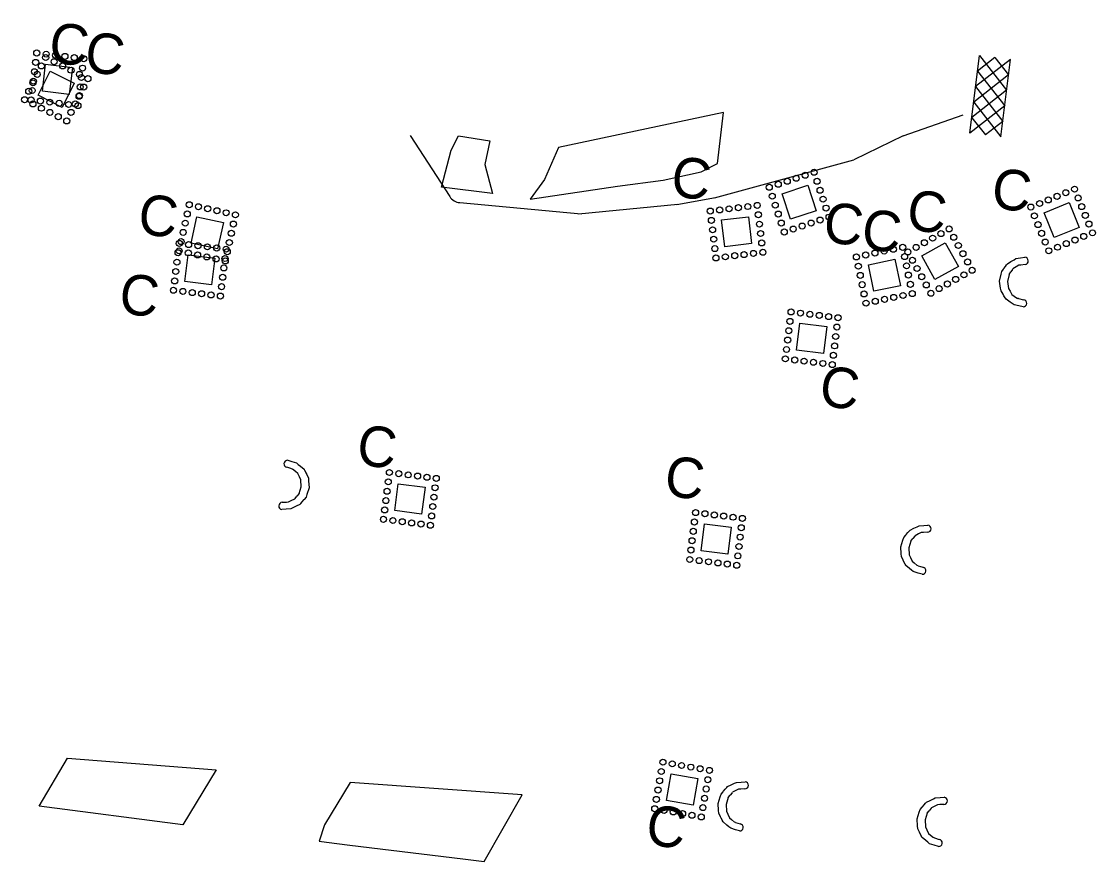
# Model space of a CAD drawing. Extents: x 2470000 to 2520000, y 340000 to 380000.
# Drawn here: x 2482594.7 to 2482992.6, y 365832.6 to 366143.9 of the extents above; entities that cross this region are included whole.
import ezdxf

# ---------------------------------------------------------------- set-up
doc = ezdxf.new("R2010")
doc.units = 0
for name, color, linetype in [('ESA Hatching CG', 7, 'Continuous'), ('Label C CG CELL', 7, 'Continuous'), ('Prop Guardrail', 7, 'Continuous'), ('Prop Guardrail Anchor Unit CELL', 7, 'Continuous'), ('Prop Structure Anchor Unit CELL', 7, 'Continuous'), ('Rock Inlet Sediment Trap Type C CG CELL', 7, 'Continuous'), ('Rock Silt Check Type A Final CELL', 7, 'Continuous'), ('Scratch_Level_5', 7, 'Continuous'), ('Sheet Data Field CELL', 7, 'Continuous'), ('Wattle Both CELL', 7, 'Continuous'), ('Wattle CG CELL', 7, 'Continuous')]:
    doc.layers.add(name, color=color, linetype=linetype)

# ---------------------------------------------------------------- blocks, each defined once
blk = doc.blocks.new('C2')
at = {"layer": 'Prop Guardrail Anchor Unit CELL'}
blk.add_text('C', height=0.3, dxfattribs=at).set_placement((-0.161, -0.136))
blk = doc.blocks.new('C3')
at = {"layer": 'Prop Guardrail'}
blk.add_text('C', height=0.3, dxfattribs=at).set_placement((-0.161, -0.136))
blk = doc.blocks.new('C1')
at = {"layer": 'Label C CG CELL'}
blk.add_text('C', height=0.3, dxfattribs=at).set_placement((-0.161, -0.136))

msp = doc.modelspace()

# ---------------------------------------------------------------- linework, layer by layer
at = {"layer": 'ESA Hatching CG'}
for points in [[(2482783.17, 366078.02), (2482815.48, 366082.81), (2482832.39, 366085.11), (2482846.44, 366088.2), (2482852.5, 366091.17), (2482854.82, 366110.14), (2482793.62, 366097.16), (2482788.43, 366085.25)], [(2482768.25, 366099.58), (2482766.41, 366090.91), (2482769.18, 366080.17), (2482750.25, 366082.49), (2482753.9, 366096.19), (2482756.63, 366101.54)], [(2482666.88, 365866.58), (2482654.45, 365846.17), (2482601.26, 365853.13), (2482611.74, 365870.81)], [(2482716.53, 365861.91), (2482706.94, 365846.13), (2482704.95, 365840.13), (2482707.69, 365839.74), (2482716.32, 365838.68), (2482758.24, 365833.54), (2482766.16, 365832.57), (2482780.17, 365857.27)]]:
    msp.add_lwpolyline(points, close=True, dxfattribs=at)
at = {"layer": 'Prop Structure Anchor Unit CELL'}
for points in [[(2482847.68, 365957.67), (2482857.61, 365956.45), (2482856.39, 365946.52), (2482846.46, 365947.75)], [(2482835.37, 365865.01), (2482845.22, 365863.28), (2482843.48, 365853.43), (2482833.63, 365855.18)]]:
    msp.add_lwpolyline(points, close=True, dxfattribs=at)
for centre in [(2482844.41, 365961.86), (2482847.88, 365961.44), (2482851.36, 365961.01), (2482854.83, 365960.58), (2482858.31, 365960.16), (2482861.78, 365959.73), (2482843.98, 365958.39), (2482861.35, 365956.26), (2482843.13, 365951.44), (2482843.56, 365954.92), (2482860.93, 365952.78), (2482842.7, 365947.97), (2482860.5, 365949.31), (2482842.28, 365944.49), (2482845.75, 365944.07), (2482849.22, 365943.64), (2482852.7, 365943.21), (2482860.07, 365945.83), (2482856.17, 365942.79), (2482859.65, 365942.36), (2482832.32, 365869.38), (2482835.77, 365868.77), (2482839.21, 365868.16), (2482842.66, 365867.55), (2482831.71, 365865.93), (2482846.11, 365866.95), (2482849.56, 365866.34), (2482831.1, 365862.48), (2482848.95, 365862.89), (2482829.89, 365855.59), (2482830.5, 365859.04), (2482847.73, 365856), (2482848.34, 365859.44), (2482829.28, 365852.14), (2482832.73, 365851.54), (2482847.12, 365852.55), (2482836.17, 365850.93), (2482839.62, 365850.32), (2482843.07, 365849.71), (2482846.52, 365849.1)]:
    msp.add_circle(centre, 1.12, dxfattribs=at)
at = {"layer": 'Rock Inlet Sediment Trap Type C CG CELL'}
for points in [[(2482603.65, 366127.98), (2482613.58, 366126.76), (2482612.36, 366116.83), (2482602.44, 366118.06)], [(2482876.49, 366080.05), (2482885.98, 366083.21), (2482889.14, 366073.72), (2482879.64, 366070.58)], [(2482928.18, 366056.98), (2482936.92, 366061.85), (2482941.78, 366053.12), (2482933.04, 366048.26)], [(2482883.08, 366032.01), (2482893, 366030.79), (2482891.78, 366020.87), (2482881.86, 366022.1)]]:
    msp.add_lwpolyline(points, close=True, dxfattribs=at)
for centre in [(2482600.38, 366132.18), (2482603.86, 366131.75), (2482607.33, 366131.32), (2482610.8, 366130.9), (2482614.28, 366130.47), (2482617.75, 366130.04), (2482599.96, 366128.7), (2482617.33, 366126.57), (2482599.53, 366125.23), (2482616.9, 366123.1), (2482598.68, 366118.28), (2482599.1, 366121.75), (2482616.47, 366119.62), (2482598.25, 366114.81), (2482601.72, 366114.38), (2482616.05, 366116.15), (2482605.2, 366113.95), (2482608.67, 366113.53), (2482612.14, 366113.1), (2482615.62, 366112.67), (2482885.02, 366086.86), (2482888.34, 366087.97), (2482871.73, 366082.44), (2482875.05, 366083.55), (2482878.37, 366084.65), (2482881.69, 366085.76), (2482889.44, 366084.65), (2482872.84, 366079.12), (2482890.55, 366081.33), (2482873.94, 366075.8), (2482891.65, 366078.01), (2482892.76, 366074.69), (2482875.05, 366072.48), (2482893.87, 366071.36), (2482876.16, 366069.16), (2482880.58, 366066.94), (2482883.9, 366068.05), (2482887.22, 366069.15), (2482890.54, 366070.26), (2482938.35, 366066.97), (2482877.26, 366065.84), (2482932.24, 366063.56), (2482935.29, 366065.26), (2482940.05, 366063.91), (2482923.06, 366058.45), (2482926.12, 366060.15), (2482929.18, 366061.85), (2482941.76, 366060.85), (2482924.77, 366055.39), (2482943.46, 366057.79), (2482945.17, 366054.74), (2482926.47, 366052.33), (2482946.87, 366051.68), (2482928.18, 366049.27), (2482937.7, 366046.57), (2482940.76, 366048.27), (2482943.81, 366049.97), (2482929.88, 366046.22), (2482931.58, 366043.16), (2482934.64, 366044.86), (2482879.81, 366036.21), (2482883.28, 366035.78), (2482886.75, 366035.36), (2482890.23, 366034.93), (2482879.38, 366032.73), (2482893.7, 366034.5), (2482896.75, 366030.6), (2482897.18, 366034.08), (2482878.95, 366029.26), (2482896.32, 366027.13), (2482878.53, 366025.79), (2482895.9, 366023.65), (2482877.67, 366018.84), (2482878.1, 366022.31), (2482895.47, 366020.18), (2482881.15, 366018.41), (2482884.62, 366017.99), (2482888.09, 366017.56), (2482891.57, 366017.13), (2482895.04, 366016.71)]:
    msp.add_circle(centre, 1.12, dxfattribs=at)
at = {"layer": 'Rock Silt Check Type A Final CELL'}
for p, q in [((2482946.05, 366102.53), (2482949.57, 366131.22)), ((2482949.57, 366131.22), (2482959.63, 366118.35)), ((2482961.04, 366129.81), (2482948.17, 366119.75)), ((2482955.28, 366130.53), (2482948.86, 366125.46)), ((2482955.28, 366130.53), (2482960.33, 366124.05)), ((2482957.52, 366101.13), (2482961.04, 366129.81)), ((2482960.33, 366124.05), (2482947.46, 366114)), ((2482948.86, 366125.46), (2482958.92, 366112.59)), ((2482948.17, 366119.75), (2482958.22, 366106.83)), ((2482959.63, 366118.35), (2482946.75, 366108.24)), ((2482958.92, 366112.59), (2482946.05, 366102.53)), ((2482947.46, 366114), (2482957.52, 366101.13)), ((2482946.8, 366108.18), (2482951.76, 366101.82)), ((2482958.22, 366106.83), (2482951.76, 366101.82))]:
    msp.add_line(p, q, dxfattribs=at)
at = {"layer": 'Scratch_Level_5'}
for points in [[(2482605.35, 366125.45), (2482614.29, 366120.97), (2482609.81, 366112.03), (2482600.87, 366116.52)], [(2482973.52, 366073.01), (2482982.77, 366076.81), (2482986.57, 366067.56), (2482977.31, 366063.77)], [(2482854.05, 366070.31), (2482863.98, 366071.51), (2482865.18, 366061.59), (2482855.25, 366060.4)], [(2482659.72, 366071.47), (2482669.49, 366069.33), (2482667.34, 366059.56), (2482657.58, 366061.71)], [(2482656.42, 366057.42), (2482666.35, 366056.2), (2482665.13, 366046.28), (2482655.21, 366047.51)], [(2482908.45, 366053.68), (2482918.24, 366055.72), (2482920.27, 366045.92), (2482910.47, 366043.9)], [(2482734.27, 365972.52), (2482744.19, 365971.27), (2482742.93, 365961.34), (2482733.01, 365962.61)]]:
    msp.add_lwpolyline(points, close=True, dxfattribs=at)
for centre in [(2482603.68, 366130.51), (2482602.11, 366127.38), (2482606.81, 366128.94), (2482609.94, 366127.37), (2482600.54, 366124.25), (2482613.06, 366125.8), (2482616.19, 366124.23), (2482619.32, 366122.66), (2482598.97, 366121.12), (2482617.75, 366119.54), (2482595.84, 366114.86), (2482597.4, 366117.99), (2482616.19, 366116.41), (2482598.97, 366113.29), (2482602.09, 366111.72), (2482605.22, 366110.16), (2482613.05, 366110.15), (2482614.62, 366113.28), (2482608.35, 366108.59), (2482611.48, 366107.02), (2482978.32, 366079.06), (2482981.56, 366080.39), (2482984.8, 366081.72), (2482986.13, 366078.48), (2482656.86, 366075.96), (2482660.27, 366075.21), (2482663.69, 366074.46), (2482856.82, 366074.44), (2482860.3, 366074.86), (2482863.77, 366075.28), (2482867.25, 366075.7), (2482968.61, 366075.07), (2482971.85, 366076.4), (2482975.08, 366077.73), (2482987.46, 366075.25), (2482656.11, 366072.54), (2482667.11, 366073.71), (2482670.53, 366072.96), (2482673.95, 366072.21), (2482849.87, 366073.6), (2482853.35, 366074.02), (2482867.67, 366072.23), (2482969.94, 366071.83), (2482988.79, 366072.01), (2482655.36, 366069.12), (2482673.2, 366068.79), (2482850.29, 366070.13), (2482850.71, 366066.66), (2482868.09, 366068.76), (2482971.27, 366068.59), (2482990.12, 366068.77), (2482654.61, 366065.7), (2482672.45, 366065.37), (2482851.13, 366063.18), (2482868.51, 366065.28), (2482972.6, 366065.36), (2482984.97, 366062.87), (2482988.21, 366064.2), (2482991.45, 366065.53), (2482653.11, 366058.86), (2482653.15, 366061.62), (2482653.86, 366062.28), (2482656.63, 366061.19), (2482660.1, 366060.77), (2482663.58, 366060.34), (2482667.05, 366059.91), (2482670.52, 366059.49), (2482670.95, 366058.53), (2482671.7, 366061.95), (2482851.55, 366059.71), (2482868.93, 366061.81), (2482914.28, 366058.74), (2482917.71, 366059.45), (2482921.14, 366060.17), (2482973.93, 366062.12), (2482975.26, 366058.88), (2482978.5, 366060.21), (2482981.73, 366061.54), (2482652.3, 366054.67), (2482652.73, 366058.15), (2482656.52, 366058.11), (2482659.94, 366057.36), (2482663.36, 366056.61), (2482666.78, 366055.86), (2482670.1, 366056.01), (2482670.2, 366055.11), (2482851.97, 366056.23), (2482855.45, 366056.65), (2482858.92, 366057.07), (2482862.4, 366057.49), (2482865.87, 366057.91), (2482869.35, 366058.33), (2482904, 366056.61), (2482907.43, 366057.32), (2482910.85, 366058.03), (2482921.85, 366056.74), (2482651.87, 366051.2), (2482669.67, 366052.54), (2482904.71, 366053.18), (2482922.56, 366053.31), (2482651.45, 366047.72), (2482669.24, 366049.06), (2482905.42, 366049.76), (2482923.27, 366049.88), (2482651.02, 366044.25), (2482654.49, 366043.82), (2482657.97, 366043.4), (2482661.44, 366042.97), (2482664.92, 366042.54), (2482668.82, 366045.59), (2482906.13, 366046.33), (2482906.84, 366042.9), (2482923.98, 366046.46), (2482924.69, 366043.03), (2482668.39, 366042.12), (2482907.55, 366039.48), (2482910.98, 366040.19), (2482914.41, 366040.9), (2482917.84, 366041.61), (2482921.26, 366042.32), (2482731.01, 365976.73), (2482734.48, 365976.29), (2482737.96, 365975.85), (2482741.43, 365975.41), (2482744.9, 365974.97), (2482730.57, 365973.26), (2482747.93, 365971.06), (2482748.37, 365974.53), (2482730.13, 365969.78), (2482747.49, 365967.59), (2482729.69, 365966.31), (2482747.05, 365964.12), (2482728.81, 365959.37), (2482729.25, 365962.84), (2482746.62, 365960.64), (2482732.29, 365958.93), (2482735.76, 365958.49), (2482739.23, 365958.05), (2482742.7, 365957.61), (2482746.18, 365957.17)]:
    msp.add_circle(centre, 1.12, dxfattribs=at)
at = {"layer": 'Sheet Data Field CELL'}
for p, q in [((2482921.28, 366101.43), (2482943.54, 366109.3)), ((2482738.64, 366101.6), (2482753.33, 366078.99)), ((2482921.28, 366101.43), (2482903.07, 366092.59)), ((2482851.41, 366078.54), (2482903.07, 366092.59)), ((2482757.06, 366076.74), (2482802.05, 366072.55)), ((2482801.1, 366072.54), (2482837.85, 366076.12)), ((2482837.45, 366076.07), (2482851.84, 366078.64))]:
    msp.add_line(p, q, dxfattribs=at)
msp.add_arc((2482757.52, 366081.71), 5, 213.0274, 264.68, dxfattribs=at)
at = {"layer": 'Wattle Both CELL'}
for p, q in [((2482694.82, 365978.1), (2482693.05, 365978.67)), ((2482694.82, 365978.1), (2482695.14, 365978)), ((2482696.27, 365977.05), (2482695.14, 365978)), ((2482697.06, 365976.39), (2482696.27, 365977.05)), ((2482697.67, 365975.08), (2482697.06, 365976.39)), ((2482698.18, 365973.99), (2482697.67, 365975.08)), ((2482698.29, 365971.45), (2482698.18, 365973.99)), ((2482697.52, 365968.92), (2482696.77, 365968)), ((2482697.52, 365968.92), (2482698.29, 365971.44)), ((2482698.29, 365971.45), (2482698.29, 365971.44)), ((2482691.3, 365965.68), (2482692.85, 365965.76)), ((2482692.85, 365965.76), (2482693.64, 365965.81)), ((2482693.64, 365965.81), (2482694.63, 365966.3)), ((2482694.63, 365966.3), (2482695.93, 365966.95)), ((2482696.08, 365967.13), (2482695.93, 365966.95)), ((2482696.08, 365967.13), (2482696.77, 365968)), ((2482924.15, 365951.33), (2482924.9, 365952.26)), ((2482925.6, 365953.12), (2482924.9, 365952.26)), ((2482925.6, 365953.12), (2482925.75, 365953.3)), ((2482927.05, 365953.95), (2482925.75, 365953.3)), ((2482928.03, 365954.44), (2482927.05, 365953.95)), ((2482928.82, 365954.49), (2482928.03, 365954.44)), ((2482930.37, 365954.57), (2482928.82, 365954.49)), ((2482924.15, 365951.33), (2482923.38, 365948.82)), ((2482923.38, 365948.8), (2482923.38, 365948.82)), ((2482923.38, 365948.8), (2482923.5, 365946.27)), ((2482923.5, 365946.27), (2482924, 365945.17)), ((2482924, 365945.17), (2482924.61, 365943.86)), ((2482924.61, 365943.86), (2482925.4, 365943.2)), ((2482925.4, 365943.2), (2482926.54, 365942.26)), ((2482926.85, 365942.16), (2482926.54, 365942.26)), ((2482926.85, 365942.16), (2482928.63, 365941.59)), ((2482856.5, 365856.24), (2482857.24, 365857.17)), ((2482857.94, 365858.03), (2482857.24, 365857.17)), ((2482857.94, 365858.03), (2482858.09, 365858.21)), ((2482859.39, 365858.86), (2482858.09, 365858.21)), ((2482860.38, 365859.35), (2482859.39, 365858.86)), ((2482861.17, 365859.4), (2482860.38, 365859.35)), ((2482862.72, 365859.48), (2482861.17, 365859.4)), ((2482856.5, 365856.24), (2482855.72, 365853.72)), ((2482855.72, 365853.71), (2482855.72, 365853.72)), ((2482855.72, 365853.71), (2482855.84, 365851.17)), ((2482933.08, 365853.11), (2482931.78, 365852.46)), ((2482934.07, 365853.6), (2482933.08, 365853.11)), ((2482934.86, 365853.64), (2482934.07, 365853.6)), ((2482936.41, 365853.73), (2482934.86, 365853.64)), ((2482855.84, 365851.17), (2482856.34, 365850.08)), ((2482856.34, 365850.08), (2482856.95, 365848.77)), ((2482856.95, 365848.77), (2482857.74, 365848.11)), ((2482930.19, 365850.48), (2482929.42, 365847.97)), ((2482930.19, 365850.48), (2482930.94, 365851.41)), ((2482931.63, 365852.28), (2482930.94, 365851.41)), ((2482931.63, 365852.28), (2482931.78, 365852.46)), ((2482857.74, 365848.11), (2482858.88, 365847.17)), ((2482859.2, 365847.06), (2482858.88, 365847.17)), ((2482859.2, 365847.06), (2482860.97, 365846.5)), ((2482929.42, 365847.96), (2482929.42, 365847.97)), ((2482929.42, 365847.96), (2482929.53, 365845.42)), ((2482929.53, 365845.42), (2482930.04, 365844.33)), ((2482930.04, 365844.33), (2482930.65, 365843.01)), ((2482930.65, 365843.01), (2482931.44, 365842.36)), ((2482931.44, 365842.36), (2482932.57, 365841.41)), ((2482932.89, 365841.31), (2482932.57, 365841.41)), ((2482932.89, 365841.31), (2482934.66, 365840.74))]:
    msp.add_line(p, q, dxfattribs=at)
for points in [[(2482693.36, 365981.24), (2482694.86, 365980.79), (2482696.59, 365980.26), (2482697.24, 365979.73), (2482698.02, 365979.09), (2482699.4, 365977.94), (2482699.42, 365977.91), (2482699.61, 365977.51), (2482699.65, 365977.44), (2482700.07, 365976.59), (2482700.36, 365975.99), (2482701.01, 365974.67), (2482701.08, 365973.63), (2482701.24, 365971.09), (2482701.24, 365971.08), (2482700.44, 365968.57), (2482700.12, 365967.59), (2482699.39, 365966.73), (2482699.23, 365966.54), (2482698.61, 365965.81), (2482698.13, 365965.26), (2482698.02, 365965.13), (2482697.78, 365964.85), (2482697.78, 365964.85), (2482696.41, 365964.19), (2482695.21, 365963.6), (2482694.48, 365963.25), (2482692.72, 365963.13), (2482691.18, 365963.02)], [(2482928.31, 365939.01), (2482926.82, 365939.46), (2482925.08, 365939.99), (2482924.44, 365940.52), (2482923.66, 365941.17), (2482922.27, 365942.31), (2482922.26, 365942.35), (2482922.06, 365942.74), (2482922.03, 365942.81), (2482921.6, 365943.67), (2482921.31, 365944.27), (2482920.67, 365945.58), (2482920.6, 365946.62), (2482920.43, 365949.17), (2482920.43, 365949.18), (2482921.24, 365951.69), (2482921.55, 365952.67), (2482922.29, 365953.53), (2482922.44, 365953.71), (2482923.07, 365954.44), (2482923.54, 365955), (2482923.65, 365955.12), (2482923.89, 365955.4), (2482923.9, 365955.41), (2482925.26, 365956.07), (2482926.47, 365956.65), (2482927.2, 365957), (2482928.95, 365957.12), (2482930.49, 365957.23)], [(2482860.65, 365843.92), (2482859.16, 365844.37), (2482857.42, 365844.9), (2482856.78, 365845.43), (2482856, 365846.08), (2482854.62, 365847.22), (2482854.6, 365847.26), (2482854.4, 365847.65), (2482854.37, 365847.72), (2482853.95, 365848.58), (2482853.65, 365849.18), (2482853.01, 365850.49), (2482852.94, 365851.53), (2482852.77, 365854.07), (2482852.77, 365854.09), (2482853.58, 365856.6), (2482853.9, 365857.58), (2482854.63, 365858.44), (2482854.79, 365858.62), (2482855.41, 365859.35), (2482855.88, 365859.9), (2482856, 365860.03), (2482856.24, 365860.31), (2482856.24, 365860.32), (2482857.6, 365860.98), (2482858.81, 365861.56), (2482859.54, 365861.91), (2482861.29, 365862.03), (2482862.84, 365862.14)], [(2482934.35, 365838.16), (2482932.85, 365838.62), (2482931.12, 365839.14), (2482930.47, 365839.68), (2482929.69, 365840.32), (2482928.31, 365841.46), (2482928.29, 365841.5), (2482928.1, 365841.9), (2482928.06, 365841.96), (2482927.64, 365842.82), (2482927.35, 365843.42), (2482926.7, 365844.73), (2482926.63, 365845.77), (2482926.47, 365848.32), (2482926.47, 365848.33), (2482927.27, 365850.84), (2482927.59, 365851.82), (2482928.32, 365852.68), (2482928.48, 365852.86), (2482929.1, 365853.59), (2482929.58, 365854.15), (2482929.69, 365854.28), (2482929.93, 365854.56), (2482929.93, 365854.56), (2482931.29, 365855.22), (2482932.5, 365855.8), (2482933.23, 365856.15), (2482934.98, 365856.28), (2482936.53, 365856.39)]]:
    msp.add_lwpolyline(points, dxfattribs=at)
for centre, radius, start, end in [((2482693.21, 365979.96), 1.3, 83.0023, 263.0023), ((2482691.34, 365964.35), 1.33, 91.8897, 263.0023), ((2482930.33, 365955.91), 1.33, 271.8897, 83.0023), ((2482928.47, 365940.3), 1.3, 263.0023, 83.0023), ((2482862.67, 365860.82), 1.33, 271.8897, 83.0023), ((2482936.37, 365855.06), 1.33, 271.8897, 83.0023), ((2482860.81, 365845.21), 1.3, 263.0023, 83.0023), ((2482934.5, 365839.45), 1.3, 263.0023, 83.0023)]:
    msp.add_arc(centre, radius, start, end, dxfattribs=at)
at = {"layer": 'Wattle CG CELL'}
for p, q in [((2482961.83, 366051.97), (2482961.21, 366051.05)), ((2482961.83, 366051.97), (2482961.96, 366052.17)), ((2482963.2, 366052.92), (2482961.96, 366052.17)), ((2482964.15, 366053.5), (2482963.2, 366052.92)), ((2482964.93, 366053.61), (2482964.15, 366053.5)), ((2482966.47, 366053.83), (2482964.93, 366053.61)), ((2482960.54, 366050.07), (2482959.99, 366047.49)), ((2482960.54, 366050.07), (2482961.21, 366051.05)), ((2482959.99, 366047.48), (2482959.99, 366047.49)), ((2482959.99, 366047.48), (2482960.32, 366044.96)), ((2482960.32, 366044.96), (2482960.91, 366043.92)), ((2482960.91, 366043.92), (2482961.63, 366042.66)), ((2482961.63, 366042.66), (2482962.47, 366042.07)), ((2482962.47, 366042.07), (2482963.69, 366041.23)), ((2482964.01, 366041.15), (2482963.69, 366041.23)), ((2482964.01, 366041.15), (2482965.83, 366040.74))]:
    msp.add_line(p, q, dxfattribs=at)
msp.add_lwpolyline([(2482965.73, 366038.14), (2482964.2, 366038.47), (2482962.43, 366038.85), (2482961.74, 366039.32), (2482960.91, 366039.9), (2482959.43, 366040.92), (2482959.41, 366040.95), (2482959.19, 366041.33), (2482959.15, 366041.4), (2482958.65, 366042.22), (2482958.31, 366042.79), (2482957.56, 366044.04), (2482957.4, 366045.07), (2482957.02, 366047.59), (2482957.02, 366047.61), (2482957.61, 366050.18), (2482957.84, 366051.18), (2482958.5, 366052.1), (2482958.64, 366052.29), (2482959.2, 366053.07), (2482959.62, 366053.67), (2482959.73, 366053.8), (2482959.94, 366054.1), (2482959.94, 366054.11), (2482961.24, 366054.88), (2482962.4, 366055.56), (2482963.1, 366055.98), (2482964.83, 366056.25), (2482966.36, 366056.48)], dxfattribs=at)
for centre, radius, start in [((2482966.31, 366055.15), 1.33, 276.7469), ((2482965.78, 366039.44), 1.3, 267.8595)]:
    msp.add_arc(centre, radius, start, 87.8595, dxfattribs=at)

# ---------------------------------------------------------------- block references
at = {"layer": 'Label C CG CELL', "xscale": 49.99999999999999, "yscale": 50.00000000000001}
for p, rotation in [((2482626.42, 366131.14), -6.997703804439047), ((2482930.92, 366072.62), -6.997703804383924), ((2482900.02, 366068.05), -6.997703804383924), ((2482898.6, 366007.34), -6.997703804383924)]:
    msp.add_blockref('C1', p, dxfattribs=dict(at, rotation=rotation))
at = {"layer": 'Prop Structure Anchor Unit CELL', "xscale": 49.99999999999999, "yscale": 50.00000000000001, "rotation": -6.997703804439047}
for p in [(2482841.19, 365974), (2482834.32, 365844.7)]:
    msp.add_blockref('C2', p, dxfattribs=at)
at = {"layer": 'Scratch_Level_5'}
for name, p, xscale, yscale, rotation in [('C2', (2482613.14, 366134.64), 50.00000000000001, 49.99999999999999, -6.997703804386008), ('C3', (2482843.59, 366085), 49.99999999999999, 50.00000000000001, -6.997703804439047), ('C3', (2482962.33, 366080.62), 49.99999999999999, 50.00000000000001, -6.997703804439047), ('C3', (2482646.15, 366071.07), 49.99999999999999, 50.00000000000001, -6.997703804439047), ('C3', (2482914.17, 366065.47), 49.99999999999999, 50.00000000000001, -6.997703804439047), ('C3', (2482639.14, 366041.64), 49.99999999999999, 50.00000000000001, -6.997703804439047), ('C3', (2482727.2, 365985.51), 49.99999999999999, 50.00000000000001, -6.997703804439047)]:
    msp.add_blockref(name, p, dxfattribs=dict(at, xscale=xscale, yscale=yscale, rotation=rotation))

doc.saveas('drawing.dxf')
